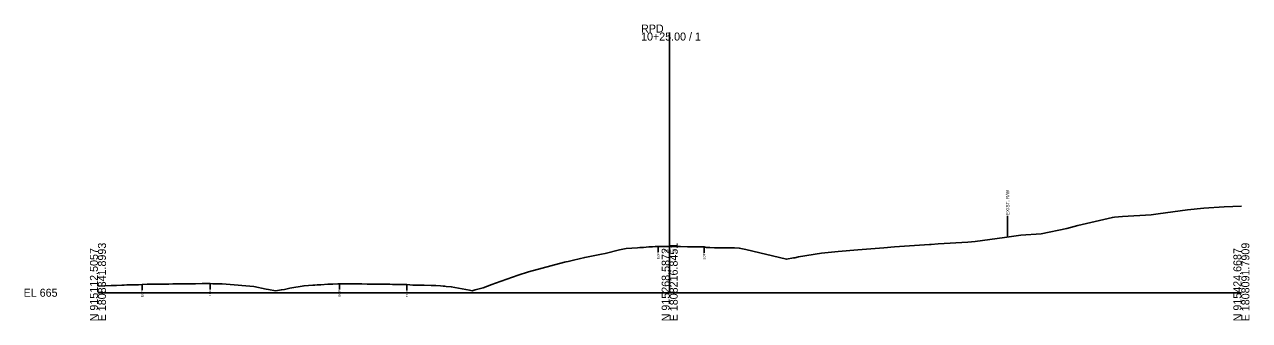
# Model space of a CAD drawing. Extents: x -26 to 403, y -10 to 8517.
# Drawn here: x -25.7 to 402.8, y 490.3 to 593.7 of the extents above; entities that cross this region are included whole.
import ezdxf

# ---------------------------------------------------------------- set-up
doc = ezdxf.new("R2010")
doc.units = 0
for name, color, linetype in [('Exist Cross Section Cell', 7, 'Continuous'), ('Exist XS Center Line Elevation Label', 7, 'Continuous'), ('Exist XS Ground Line', 7, 'Continuous'), ('Old_Level_10', 7, 'Continuous')]:
    doc.layers.add(name, color=color, linetype=linetype)

msp = doc.modelspace()

# ---------------------------------------------------------------- linework, layer by layer
at = {"layer": 'Exist Cross Section Cell'}
for p, q in [((200, 500), (200, 590.93)), ((0, 500), (200, 500)), ((200, 500), (400, 500))]:
    msp.add_line(p, q, dxfattribs=at)
at = {"layer": 'Exist XS Ground Line'}
msp.add_lwpolyline([(0, 502.28), (4.64, 502.49), (5.28, 502.52), (6.5, 502.56), (8.36, 502.66), (9.17, 502.69), (10.12, 502.73), (10.86, 502.75), (12.35, 502.77), (14.2, 502.82), (15.48, 502.93), (17.23, 502.96), (18.14, 502.97), (19.43, 502.99), (20.44, 503.01), (21.22, 503.02), (22.21, 503.03), (23.01, 503.03), (23.66, 503.04), (24.81, 503.04), (26.19, 503.07), (26.66, 503.08), (27.34, 503.08), (30.19, 503.12), (33.3, 503.16), (34.13, 503.16), (36.47, 503.18), (37.21, 503.19), (38.14, 503.2), (39.2, 503.22), (40.2, 503.12), (40.77, 503.08), (42.19, 503.08), (43.06, 503.08), (43.41, 503.08), (44.82, 502.98), (54.59, 502.14), (58.9, 501.23), (59.68, 501.13), (62.07, 500.67), (64.19, 501.04), (65.28, 501.18), (67.14, 501.55), (72.1, 502.44), (75.23, 502.65), (75.82, 502.69), (76.66, 502.74), (77.95, 502.82), (80.37, 503), (81.5, 503.01), (82.17, 503.02), (83.97, 503.08), (84.49, 503.14), (84.99, 503.13), (86.15, 503.12), (87.03, 503.11), (87.72, 503.11), (90.15, 503.09), (90.58, 503.09), (90.93, 503.08), (92.36, 503.07), (94.17, 503.05), (94.52, 503.05), (96.5, 503.02), (97.56, 503.01), (98.12, 503), (100.56, 502.96), (102.12, 502.94), (103.02, 502.92), (103.75, 502.91), (104.82, 502.89), (106.13, 502.86), (106.96, 502.85), (108.11, 502.84), (110.18, 502.68), (111.93, 502.65), (113.4, 502.61), (113.71, 502.61), (114.09, 502.6), (116.57, 502.54), (117.92, 502.49), (118.23, 502.48), (119.84, 502.37), (120.81, 502.3), (121.38, 502.26), (121.76, 502.23), (123.6, 502.11), (129.94, 500.87), (130.9, 500.68), (132, 501.02), (134.73, 501.76), (137.74, 502.86), (139.08, 503.36), (146.98, 506.13), (150.56, 507.28), (163.19, 510.68), (163.76, 510.82), (164.46, 510.97), (166.38, 511.42), (170.3, 512.32), (176.18, 513.49), (177.42, 513.76), (182.5, 514.95), (184.75, 515.46), (188.77, 515.71), (189.51, 515.77), (190.82, 515.86), (192.69, 515.99), (193.57, 516.01), (194.05, 516.04), (194.94, 516.11), (196.02, 516.2), (196.34, 516.19), (198.1, 516.17), (200, 516.15), (200.85, 516.14), (202.12, 516.12), (202.88, 516.11), (203.78, 516.11), (206.25, 516.07), (206.93, 516.06), (209.73, 516.02), (210.08, 516.02), (212.05, 515.99), (212.94, 515.85), (214.09, 515.78), (215.71, 515.73), (216.38, 515.71), (219.71, 515.68), (221.93, 515.65), (222.66, 515.65), (224.33, 515.63), (226.64, 515.11), (240.83, 511.69), (243.33, 512.19), (243.74, 512.24), (245.11, 512.55), (253.07, 513.84), (258.93, 514.41), (265.88, 515.02), (274.92, 515.73), (278.69, 516.05), (290.91, 516.84), (291.51, 516.89), (293.9, 517.04), (304.32, 517.68), (306.91, 517.96), (317.13, 519.27), (322.9, 520.08), (329.95, 520.58), (338.89, 522.43), (342.76, 523.53), (354.88, 526.3), (355.58, 526.39), (358.36, 526.59), (368.39, 527.28), (370.88, 527.53), (381.2, 528.92), (386.87, 529.51), (394.02, 530), (400, 530.31)], dxfattribs=at)
at = {"layer": 'Old_Level_10'}
for p, q in [((318.24, 526.83), (318.24, 519.43)), ((196.02, 516.2), (196.02, 514.14)), ((212.05, 515.99), (212.05, 513.94)), ((15.48, 502.93), (15.48, 500.88)), ((39.2, 503.22), (39.2, 501.17)), ((84.49, 503.14), (84.49, 501.09)), ((108.11, 502.84), (108.11, 500.79))]:
    msp.add_line(p, q, dxfattribs=at)

# ---------------------------------------------------------------- texts
at = {"layer": 'Exist Cross Section Cell'}
for s, p in [('RPD', (190, 590.93)), ('10+25.00 / 1', (190, 588.13)), ('EL 665', (-26, 498.6))]:
    msp.add_text(s, height=2.8, dxfattribs=at).set_placement(p)
for s, p in [('N 915112.5057', (0, 490)), ('E 1808341.8993', (2.8, 490)), ('N 915268.5872', (200, 490)), ('E 1808216.8451', (202.8, 490)), ('N 915424.6687', (400, 490)), ('E 1808091.7909', (402.8, 490))]:
    msp.add_text(s, height=2.8, rotation=90, dxfattribs=at).set_placement(p)
at = {"layer": 'Exist XS Center Line Elevation Label'}
msp.add_text('681.15', height=1, dxfattribs=at).set_placement((198.11, 514.15))
at = {"layer": 'Old_Level_10'}
for s, height, p in [('EXIST. R/W', 1.181, (318.83, 527.13)), ('EOP', 0.787, (196.41, 511.75)), ('EOP', 0.787, (212.44, 511.54)), ('EOP', 0.787, (15.87, 498.48)), ('EOP', 0.787, (39.59, 498.77)), ('EOP', 0.787, (84.89, 498.69)), ('EOP', 0.787, (108.5, 498.39))]:
    msp.add_text(s, height=height, rotation=90, dxfattribs=at).set_placement(p)

doc.saveas('drawing.dxf')
